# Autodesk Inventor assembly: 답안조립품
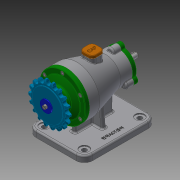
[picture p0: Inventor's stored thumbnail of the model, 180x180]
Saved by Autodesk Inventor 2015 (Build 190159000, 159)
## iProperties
Created: 2021-10
Part Number: 답안조립품
Document SubType Name: 용접물
Designer: pc-04
Weld Material: 알루미늄 6061, 용접
Author: pc-04
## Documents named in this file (16)
- C:\Users\pc-04\Desktop\711006V1010\답안조립품.iam
- C:\Users\pc-04\Desktop\711006V1010\본체.ipt
- C:\Users\pc-04\Desktop\711006V1010\뒤커버.ipt
- C:\Users\pc-04\Desktop\711006V1010\베어링 6200.ipt
- C:\Users\pc-04\Desktop\711006V1010\오일 실 10x20x7.ipt
- C:\Users\pc-04\Desktop\711006V1010\축.ipt
- C:\Users\pc-04\Desktop\711006V1010\앞커버.ipt
- C:\Users\pc-04\Desktop\711006V1010\베어링 6203.ipt
- C:\Users\pc-04\Desktop\711006V1010\오일 실 17x30x8.ipt
- C:\Users\pc-04\Desktop\711006V1010\키 5x5.ipt
- 키 5 x 5.ipt
- C:\Users\pc-04\Desktop\711006V1010\스프로킷.ipt
- C:\Users\pc-04\Desktop\711006V1010\와셔.ipt
- C:\Users\pc-04\Desktop\711006V1010\볼트 M4.ipt
- 볼트 M4 x 12.ipt
- C:\Users\pc-04\Desktop\711006V1010\마개.ipt
